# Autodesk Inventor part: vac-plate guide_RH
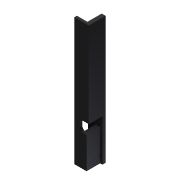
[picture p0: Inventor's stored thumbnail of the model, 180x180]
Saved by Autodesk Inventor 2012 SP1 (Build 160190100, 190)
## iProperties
Created: 2000-06
Part Number: vac-plate guide_RH
Project: BONDING PRESS
Material: Delrin, White
Description: VACUUM PLATE GUIDE L/R
Document SubType Name: Modeling
Designer: Neil
Density: 1 g/cm^3
Author: Neil
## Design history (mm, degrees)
derived "vac-plate guide.ipt"
body "Solid1"
tag "TaggingFeature2"
feature "Solid1::vac-plate guide.ipt" dims "d0" = 10
